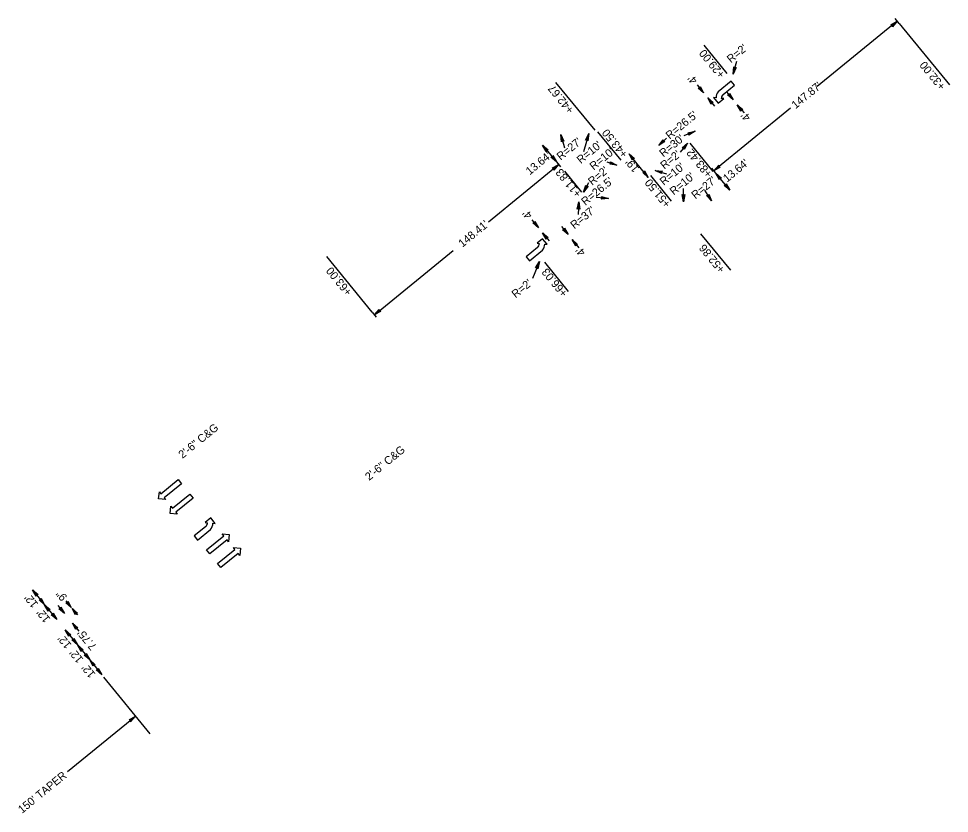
# Model space of a CAD drawing. Extents: x 2320991 to 2332664, y 598057 to 612602.
# Drawn here: x 2323803 to 2324384, y 599659 to 600155 of the extents above; entities that cross this region are included whole.
import ezdxf

# ---------------------------------------------------------------- set-up
doc = ezdxf.new("R2010")
doc.units = 0
for name, color, linetype in [('Prop Dimension', 7, 'Continuous'), ('Prop Dimension Text', 7, 'Continuous'), ('Prop Lane Arrow CELL', 7, 'Continuous'), ('Prop Terminator CELL', 7, 'Continuous')]:
    doc.layers.add(name, color=color, linetype=linetype)

msp = doc.modelspace()

# ---------------------------------------------------------------- linework, layer by layer
at = {"layer": 'Prop Dimension'}
for p, q in [((2324352.93, 600151.88), (2324350.41, 600154.98)), ((2324351.67, 600153.43), (2324301.55, 600112.52)), ((2324352.93, 600151.88), (2324384.2, 600113.59)), ((2324245.48, 600120.64), (2324230.98, 600138.4)), ((2324249.07, 600120.31), (2324251.38, 600128.49)), ((2324162.96, 600085.22), (2324138.52, 600115.14)), ((2324226.61, 600113.62), (2324230.72, 600108.58)), ((2324245.1, 600109.35), (2324249.21, 600104.32)), ((2324233.25, 600105.49), (2324237.44, 600100.35)), ((2324251.74, 600101.22), (2324255.94, 600096.08)), ((2324285.02, 600099.02), (2324237.12, 600059.92)), ((2324179.16, 600066.49), (2324164.65, 600084.27)), ((2324225.34, 600084.58), (2324218.46, 600081.83)), ((2324141.45, 600082.66), (2324143.78, 600074.36)), ((2324158.98, 600083.24), (2324155.63, 600071.84)), ((2324202.66, 600075.67), (2324207.59, 600080.35)), ((2324130.11, 600076), (2324138.74, 600065.44)), ((2324220.75, 600077.27), (2324216.02, 600071.58)), ((2324222.19, 600077.09), (2324236.51, 600059.54)), ((2324196.14, 600055.83), (2324184.12, 600070.54)), ((2324096.45, 600028.13), (2324140.11, 600063.77)), ((2324138.74, 600065.44), (2324141.27, 600062.34)), ((2324170.31, 600065.49), (2324176.6, 600063.34)), ((2324238.39, 600058.37), (2324235.86, 600061.47)), ((2324154.72, 600046.54), (2324143.98, 600059.69)), ((2324197.46, 600056.91), (2324210.45, 600041.01)), ((2324200.37, 600060.19), (2324207.52, 600058.09)), ((2324247.01, 600047.8), (2324238.39, 600058.37)), ((2324155.78, 600046.67), (2324158.99, 600052.66)), ((2324218.12, 600040.56), (2324218.2, 600048.82)), ((2324171.42, 600042.56), (2324163.58, 600043.34)), ((2324235.68, 600041.15), (2324231.39, 600047.91)), ((2324152.73, 600040.49), (2324152.47, 600032.61)), ((2324123.44, 600029.39), (2324127.55, 600024.36)), ((2324130.08, 600021.26), (2324134.27, 600016.12)), ((2324141.93, 600025.13), (2324146.04, 600020.09)), ((2324228.81, 600020.65), (2324247.42, 599997.87)), ((2324148.57, 600016.99), (2324152.77, 600011.85)), ((2324025.14, 599969.91), (2324074.34, 600010.07)), ((2324128.24, 600003.18), (2324123.87, 599992.56)), ((2324131.25, 600002.85), (2324146.18, 599984.57)), ((2324023.77, 599971.59), (2324026.3, 599968.49)), ((2323811.6, 599798.22), (2323819.19, 599788.92)), ((2323819.19, 599788.92), (2323826.78, 599779.62)), ((2323827.51, 599788.44), (2323831.62, 599783.41)), ((2323832.51, 599791.22), (2323835.82, 599787.16)), ((2323836.3, 599786.58), (2323839.61, 599782.53)), ((2323836.52, 599777.4), (2323840.63, 599772.37)), ((2323832.06, 599773.15), (2323839.65, 599763.86)), ((2323839.74, 599763.74), (2323847.33, 599754.45)), ((2323847.33, 599754.45), (2323854.92, 599745.15)), ((2323856.02, 599743.63), (2323884.93, 599708.22)), ((2323833.55, 599684.7), (2323875.9, 599719.28))]:
    msp.add_line(p, q, dxfattribs=at)
msp.add_lwpolyline([(2324023.77, 599971.59), (2323995.32, 600006.44)], dxfattribs=at)
at = {"layer": 'Prop Lane Arrow CELL'}
for p, q in [((2324247.98, 600115.95), (2324239.81, 600109.28)), ((2324242.98, 600107.61), (2324250.07, 600113.4)), ((2324250.07, 600113.4), (2324247.98, 600115.95)), ((2324238.47, 600105.47), (2324236.99, 600105.62)), ((2324236.99, 600105.62), (2324239.73, 600102.18)), ((2324239.73, 600102.18), (2324243.25, 600104.99)), ((2324243.25, 600104.99), (2324241.77, 600105.14)), ((2324130.19, 600017.46), (2324126.67, 600014.66)), ((2324126.67, 600014.66), (2324128.15, 600014.51)), ((2324132.93, 600014.02), (2324130.19, 600017.46)), ((2324131.46, 600014.17), (2324132.93, 600014.02)), ((2324126.94, 600012.03), (2324119.85, 600006.25)), ((2324121.94, 600003.69), (2324130.11, 600010.36)), ((2324119.85, 600006.25), (2324121.94, 600003.69)), ((2323891.77, 599858.24), (2323902.64, 599867.07)), ((2323904.72, 599864.5), (2323893.85, 599855.68)), ((2323902.64, 599867.07), (2323904.72, 599864.5)), ((2323890.39, 599854.94), (2323890.82, 599859.41)), ((2323890.82, 599859.41), (2323891.77, 599858.24)), ((2323898.97, 599849.19), (2323909.84, 599858.02)), ((2323909.84, 599858.02), (2323911.92, 599855.45)), ((2323894.79, 599854.52), (2323890.39, 599854.94)), ((2323893.85, 599855.68), (2323894.79, 599854.52)), ((2323911.92, 599855.45), (2323901.05, 599846.63)), ((2323897.6, 599845.89), (2323898.03, 599850.36)), ((2323902, 599845.47), (2323897.6, 599845.89)), ((2323898.03, 599850.36), (2323898.97, 599849.19)), ((2323901.05, 599846.63), (2323902, 599845.47)), ((2323922.92, 599843.07), (2323919.41, 599840.26)), ((2323919.41, 599840.26), (2323920.88, 599840.11)), ((2323925.67, 599839.63), (2323922.92, 599843.07)), ((2323924.19, 599839.77), (2323925.67, 599839.63)), ((2323919.67, 599837.64), (2323912.59, 599831.85)), ((2323914.67, 599829.29), (2323922.84, 599835.97)), ((2323912.59, 599831.85), (2323914.67, 599829.29)), ((2323920.2, 599823.18), (2323931.07, 599832)), ((2323933.15, 599829.44), (2323922.28, 599820.61)), ((2323931.07, 599832), (2323930.13, 599833.16)), ((2323930.13, 599833.16), (2323934.53, 599832.74)), ((2323934.1, 599828.27), (2323933.15, 599829.44)), ((2323934.53, 599832.74), (2323934.1, 599828.27)), ((2323922.28, 599820.61), (2323920.2, 599823.18)), ((2323927.2, 599814.61), (2323938.07, 599823.43)), ((2323938.07, 599823.43), (2323937.13, 599824.59)), ((2323937.13, 599824.59), (2323941.52, 599824.17)), ((2323941.52, 599824.17), (2323941.1, 599819.7)), ((2323940.15, 599820.87), (2323929.28, 599812.04)), ((2323941.1, 599819.7), (2323940.15, 599820.87)), ((2323929.28, 599812.04), (2323927.2, 599814.61))]:
    msp.add_line(p, q, dxfattribs=at)
for centre, radius, start, end in [((2324243.7, 600105.77), 5.25, 137.90406, 183.21576), ((2324245.04, 600105.08), 3.27, 129.22799, 178.88617), ((2324124.89, 600014.56), 3.27, 309.22799, 358.88617), ((2324126.23, 600013.87), 5.25, 317.90406, 3.21576), ((2323917.62, 599840.17), 3.27, 309.22799, 358.88617), ((2323918.96, 599839.47), 5.25, 317.90406, 3.21576)]:
    msp.add_arc(centre, radius, start, end, dxfattribs=at)
at = {"layer": 'Prop Terminator CELL'}
for points in [[(2324347.69, 600151.19), (2324351.67, 600153.43), (2324348.67, 600149.95), (2324348.61, 600150.93)], [(2324251.03, 600124.43), (2324249.07, 600120.31), (2324249.53, 600124.89), (2324250.14, 600124.11)], [(2324228.47, 600112.56), (2324230.72, 600108.58), (2324227.24, 600111.58), (2324228.22, 600111.64)], [(2324246.97, 600108.3), (2324249.21, 600104.32), (2324245.73, 600107.32), (2324246.71, 600107.38)], [(2324235.49, 600101.51), (2324233.25, 600105.49), (2324236.73, 600102.49), (2324235.74, 600102.43)], [(2324253.99, 600097.24), (2324251.74, 600101.22), (2324255.22, 600098.22), (2324254.24, 600098.16)], [(2324220.87, 600083.62), (2324225.34, 600084.58), (2324221.43, 600082.15), (2324221.67, 600083.11)], [(2324141.92, 600078.12), (2324141.45, 600082.66), (2324143.44, 600078.52), (2324142.52, 600078.86)], [(2324156.97, 600079.14), (2324158.98, 600083.24), (2324158.48, 600078.68), (2324157.87, 600079.45)], [(2324206.46, 600078.21), (2324202.66, 600075.67), (2324205.39, 600079.36), (2324205.53, 600078.39)], [(2324132.36, 600072.03), (2324130.11, 600076), (2324133.59, 600073), (2324132.61, 600072.94)], [(2324217.28, 600074.31), (2324220.75, 600077.27), (2324218.47, 600073.28), (2324218.22, 600074.23)], [(2324136.49, 600069.42), (2324138.74, 600065.44), (2324135.25, 600068.44), (2324136.24, 600068.5)], [(2324136.49, 600069.42), (2324138.74, 600065.44), (2324135.25, 600068.44), (2324136.24, 600068.5)], [(2324186.37, 600066.57), (2324184.12, 600070.54), (2324187.6, 600067.54), (2324186.62, 600067.48)], [(2324136.13, 600061.52), (2324140.11, 600063.77), (2324137.11, 600060.29), (2324137.05, 600061.27)], [(2324172.59, 600065.53), (2324176.6, 600063.34), (2324172.06, 600064.04), (2324172.86, 600064.61)], [(2324241.1, 600062.16), (2324237.12, 600059.92), (2324240.12, 600063.4), (2324240.18, 600062.41)], [(2324193.89, 600059.8), (2324196.14, 600055.83), (2324192.66, 600058.82), (2324193.64, 600058.89)], [(2324204.47, 600058.18), (2324200.37, 600060.19), (2324204.94, 600059.69), (2324204.16, 600059.08)], [(2324240.63, 600054.39), (2324238.39, 600058.37), (2324241.87, 600055.37), (2324240.89, 600055.31)], [(2324158.59, 600050.27), (2324155.78, 600046.67), (2324157.21, 600051.03), (2324157.64, 600050.15)], [(2324244.76, 600051.78), (2324247.01, 600047.8), (2324243.53, 600050.8), (2324244.51, 600050.86)], [(2324167.02, 600043.78), (2324171.42, 600042.56), (2324166.84, 600042.21), (2324167.49, 600042.95)], [(2324218.94, 600045.05), (2324218.12, 600040.56), (2324217.37, 600045.1), (2324218.16, 600044.51)], [(2324233.92, 600045.37), (2324235.68, 600041.15), (2324232.58, 600044.54), (2324233.56, 600044.49)], [(2324151.81, 600036.02), (2324152.73, 600040.49), (2324153.38, 600035.94), (2324152.6, 600036.54)], [(2324125.3, 600028.33), (2324127.55, 600024.36), (2324124.07, 600027.36), (2324125.05, 600027.42)], [(2324132.32, 600017.28), (2324130.08, 600021.26), (2324133.56, 600018.26), (2324132.57, 600018.2)], [(2324143.8, 600024.07), (2324146.04, 600020.09), (2324142.56, 600023.09), (2324143.54, 600023.15)], [(2324150.82, 600013.02), (2324148.57, 600016.99), (2324152.05, 600013.99), (2324151.07, 600013.93)], [(2324125.81, 599999.31), (2324128.24, 600003.18), (2324127.25, 599998.69), (2324126.73, 599999.52)], [(2324029.12, 599972.16), (2324025.14, 599969.91), (2324028.14, 599973.39), (2324028.2, 599972.41)], [(2323813.85, 599794.24), (2323811.6, 599798.22), (2323815.08, 599795.22), (2323814.1, 599795.16)], [(2323816.94, 599792.9), (2323819.19, 599788.92), (2323815.71, 599791.92), (2323816.69, 599791.98)], [(2323821.44, 599784.94), (2323819.19, 599788.92), (2323822.67, 599785.92), (2323821.69, 599785.86)], [(2323829.37, 599787.38), (2323831.62, 599783.41), (2323828.14, 599786.41), (2323829.12, 599786.47)], [(2323833.58, 599791.14), (2323835.82, 599787.16), (2323832.34, 599790.16), (2323833.33, 599790.22)], [(2323824.53, 599783.6), (2323826.78, 599779.62), (2323823.3, 599782.62), (2323824.28, 599782.68)], [(2323838.54, 599782.61), (2323836.3, 599786.58), (2323839.78, 599783.58), (2323838.8, 599783.52)], [(2323838.77, 599773.43), (2323836.52, 599777.4), (2323840, 599774.41), (2323839.02, 599774.34)], [(2323834.31, 599769.18), (2323832.06, 599773.15), (2323835.54, 599770.15), (2323834.56, 599770.09)], [(2323837.4, 599767.83), (2323839.65, 599763.86), (2323836.17, 599766.86), (2323837.15, 599766.92)], [(2323841.99, 599759.77), (2323839.74, 599763.74), (2323843.22, 599760.75), (2323842.24, 599760.68)], [(2323845.09, 599758.43), (2323847.33, 599754.45), (2323843.85, 599757.45), (2323844.83, 599757.51)], [(2323849.58, 599750.47), (2323847.33, 599754.45), (2323850.81, 599751.45), (2323849.83, 599751.39)], [(2323852.68, 599749.13), (2323854.92, 599745.15), (2323851.44, 599748.15), (2323852.42, 599748.21)], [(2323871.93, 599717.03), (2323875.9, 599719.28), (2323872.9, 599715.79), (2323872.84, 599716.78)]]:
    msp.add_lwpolyline(points, close=True, dxfattribs=at)

# ---------------------------------------------------------------- texts
at = {"layer": 'Prop Dimension'}
for s, p in [('+29.00', (2324244.39, 600120.25)), ('+32.00', (2324382.11, 600112.89)), ('+42.67', (2324150.03, 600098.15)), ('+43.50', (2324183.72, 600070.57)), ('+83.42', (2324236.46, 600058.18)), ('+11.83', (2324154.78, 600045.83)), ('+51.50', (2324210.48, 600039.43)), ('+52.86', (2324244.39, 599998.6)), ('+63.00', (2324011.46, 599984.38)), ('+66.03', (2324146.09, 599983.62))]:
    msp.add_text(s, height=5, rotation=129.22799, dxfattribs=at).set_placement(p)
at = {"layer": 'Prop Dimension Text'}
for s, rotation, p in [("R=2'", 39.22799, (2324247.76, 600126.98)), ("4'", 129.22799, (2324227.28, 600116.56)), ("147.87'", 39.22799, (2324288.12, 600098.33)), ("R=26.5'", 39.22799, (2324209.55, 600079.29)), ("4'", 129.22799, (2324260.48, 600093.38)), ("R=27'", 39.22799, (2324141.47, 600066.17)), ("R=10'", 39.22799, (2324154.03, 600064.05)), ("R=30'", 39.22799, (2324205.55, 600068.19)), ("R=10'", 39.22799, (2324162.04, 600060.05)), ("R=2'", 39.22799, (2324206.2, 600060.6)), ("13.64'", 39.22799, (2324122.15, 600057.02)), ("19'", 129.22799, (2324190.83, 600061.38)), ("13.64'", 39.22799, (2324245.36, 600052.49)), ("R=2'", 39.22799, (2324161.09, 600050.56)), ("R=10'", 39.22799, (2324205.83, 600050.51)), ("R=26.5'", 39.22799, (2324156.83, 600037.99)), ("R=10'", 39.22799, (2324212.08, 600044.43)), ("R=27'", 39.22799, (2324225.6, 600042)), ("R=37'", 39.22799, (2324150.02, 600023.29)), ("4'", 129.22799, (2324124.11, 600032.33)), ("148.41'", 39.22799, (2324080.08, 600011.85)), ("4'", 129.22799, (2324157.31, 600009.15)), ("R=2'", 39.22799, (2324113.33, 599980.16)), ('2\'-6" C&G', 39.22799, (2323905.27, 599879.93)), ('2\'-6" C&G', 39.22799, (2324021.81, 599866.15)), ("12'", 129.22799, (2323815.47, 599789.39)), ('9"', 129.22799, (2323833.62, 599793.76)), ("12'", 129.22799, (2323823.06, 599780.1)), ("7.75'", 129.22799, (2323852.04, 599762.96)), ("12'", 129.22799, (2323836.3, 599763.88)), ("12'", 129.22799, (2323843.61, 599754.92)), ("12'", 129.22799, (2323851.2, 599745.63)), ("150' TAPER", 39.22799, (2323805.09, 599658.24))]:
    msp.add_text(s, height=5, rotation=rotation, dxfattribs=at).set_placement(p)

doc.saveas('drawing.dxf')
